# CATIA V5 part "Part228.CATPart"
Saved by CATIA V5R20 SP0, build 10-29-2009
Part number: 9FA 042212
Revision: ANY
Definition: UNKNOWN
Nomenclature: 9FA 042212
Source: Unknown
Bounding box of the stored display mesh (mm): x -10 to 10, y 0.13 to 20.13, z -10 to 10
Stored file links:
  C:\Users\Utente\Desktop\IO LAVORO\3D X SITO CF\CUMSA\3D files FA\FA 200712-20\Part228.CATPart
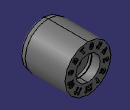
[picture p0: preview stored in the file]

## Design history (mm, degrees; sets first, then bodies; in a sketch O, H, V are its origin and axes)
Body1 "Cortar-Extruir4" (main body)
  Solid1: solid without history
